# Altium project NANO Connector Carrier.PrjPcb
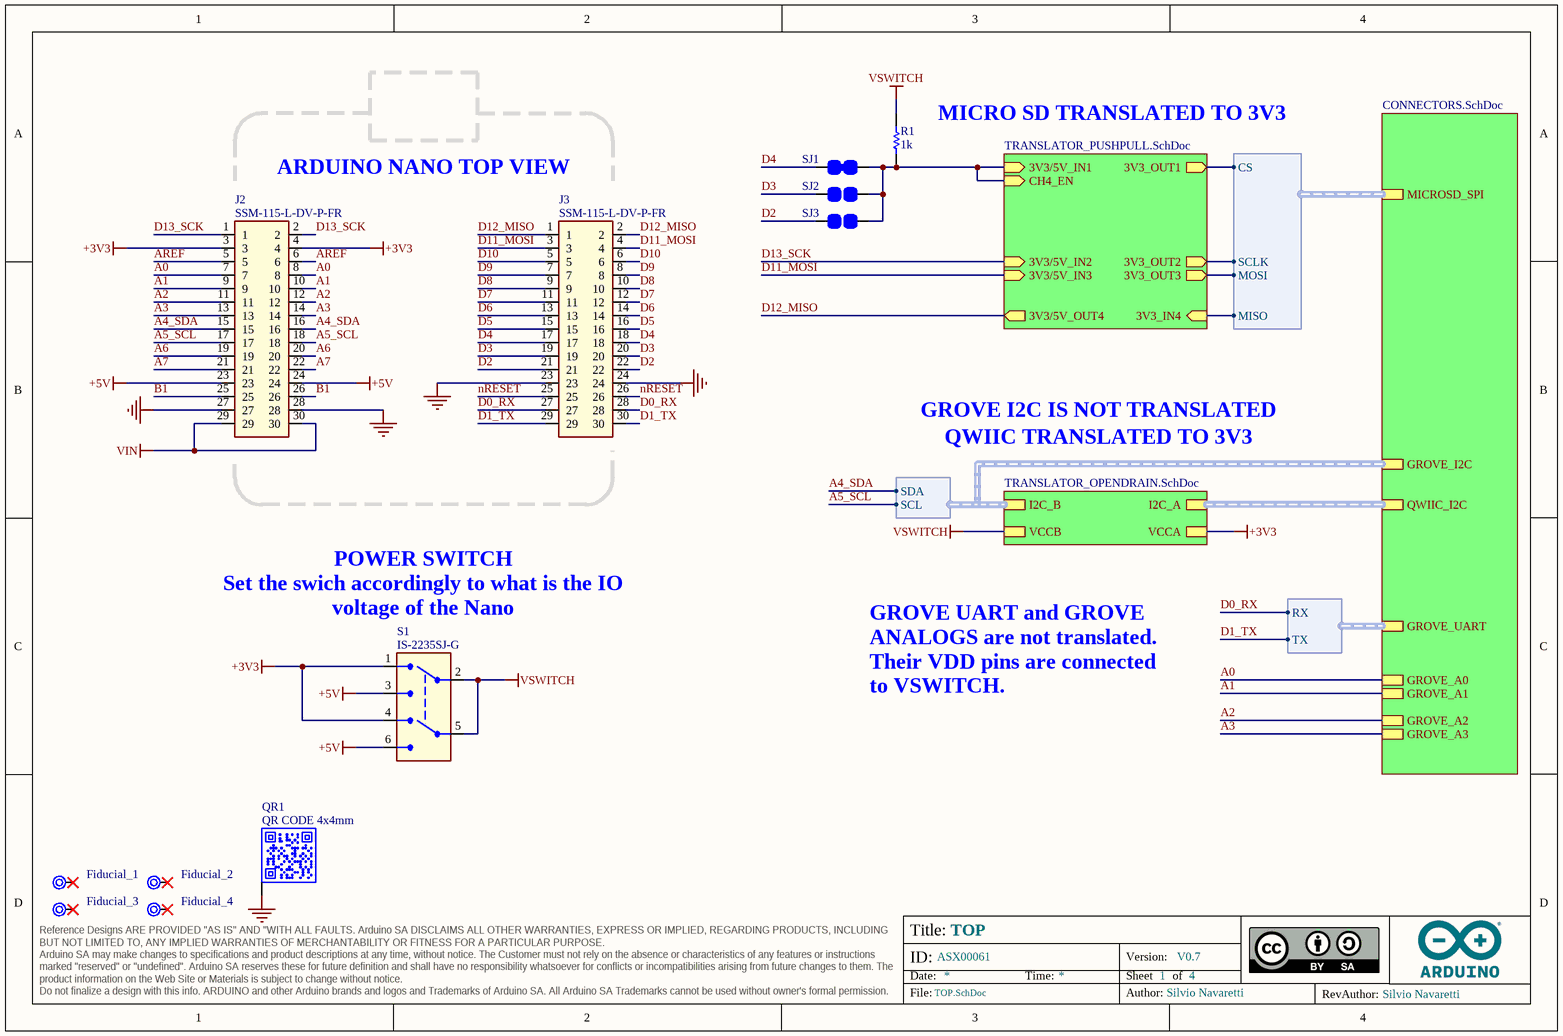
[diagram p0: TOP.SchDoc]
VIA_THROUGH_PAD_MM: 0.6; VIA_THROUGH_HOLE_MM: 0.3; VIA_THROUGH: X; VIA_5_PAD_MM: _; VIA_5_HOLE_MM: _; VIA_5: _; VIA_4_PAD_MM: _; VIA_4_HOLE_MM: _; VIA_4: _; VIA_3_PAD_MM: _; VIA_3_HOLE_MM: _; VIA_3: _; VIA_2_PAD_MM: _; VIA_2_HOLE_MM: _; VIA_2: _; VIA_1_PAD_MM: _; VIA_1_HOLE_MM: _; VIA_1: _; VERSION: V0.7; TRACK_MIN_WIDTH_OUTER: 0.15mm; TRACK_MIN_WIDTH_INNER: 0.15mm; SKU: ASX00061; PANEL_TABS: _; PANEL_SIZE: 162.23mmx182mm; PANEL_SCORING: X; PANEL_REQUESTED: _; PANEL_PROVIDED: X; PANEL_NUMBER_OF_FIGURES: 15; PANEL_NOT_REQUESTED: _; PANEL_MILLING: X; INSULATION_MIN_OUTER: 0.15mm; INSULATION_MIN_INNER: 0.15mm; FINISH_TBD: _; FINISH_TABS: _; FINISH_SOLDERMASK_TOP: X; FINISH_SOLDERMASK_PEELABLE_TOP: _; FINISH_SOLDERMASK_PEELABLE_COLOR: _; FINISH_SOLDERMASK_PEELABLE_BOTTOM: _; FINISH_SOLDERMASK_COLOR: BLUE; FINISH_SOLDERMASK_BOTTOM: X; FINISH_SN/PB: _; FINISH_SILK_TOP: X; FINISH_SILK_COLOR: WHITE; FINISH_SILK_BOTTOM: X; FINISH_NI/AU: _; FINISH_HAL_LF: X; FINISH_HAL: _; FINISH_ENIG: _; FINISH_EDGE_PLATING: _; FINISH_ADJUSTMENTS: _; DRILLS_SOLDER_FILLING: X; DRILLS_SLOT: _; DRILLS_RESIN_FILLING: _; DRILLS_PRESSFIT: _; DRILLS_LASER: _; DRILLS_FULL: X; DRILLS_COPPER_FILLING: _; DRILLS_BURIED: _; DRILLS_BLIND: _; BOARD_INFO_THICKNESS: 1.6mm; BOARD_INFO_TBD: _; BOARD_INFO_RIGID/FLEX: _; BOARD_INFO_RIGID: X; BOARD_INFO_POLYMIDE: _; BOARD_INFO_PCB_SIZE: 43.18mmx27.94mm; BOARD_INFO_NUMBER_OF_LAYERS: 2; BOARD_INFO_IPC_NA: X; BOARD_INFO_IPC3: _; BOARD_INFO_IPC2: _; BOARD_INFO_IPC1: _; BOARD_INFO_FR4_HTG: _; BOARD_INFO_FR4: X; BOARD_INFO_FLEX: _; BOARD_INFO_Er: _; BOARD_INFO_AUTHOR_REV: Silvio Navaretti; BOARD_INFO_AUTHOR: Silvio Navaretti; BOARD_CODENAME: Nano Connector Carrier; ASSEMBLY_THT: _; ASSEMBLY_SMD: X; ASSEMBLY_PRESSFIT: _; ASSEMBLY_BGA: _
4 sheets, 38 parts. Net scope: hierarchical (ports join the sheet entries above them; power ports are global).
Board files: NANO.PcbDoc, NANO_PANEL.PcbDoc
Sheets:
  TOP.SchDoc
    U_CONNECTORS = CONNECTORS.SchDoc
    U_TRANSLATOR_OPENDRAIN = TRANSLATOR_OPENDRAIN.SchDoc
    U_TRANSLATOR_PUSHPULL = TRANSLATOR_PUSHPULL.SchDoc

## Sheet TOP.SchDoc: TOP
size A4; Author: Silvio Navaretti; Revision: V0.1; SheetNumber: 1; SheetTotal: 4; RevAuthor: Silvio Navaretti

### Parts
Fiducial_1  Fiducial mark 1mm with 2mm solder  [Fiducial mark 1mm with circle-Footprint-1]  (value not drawn)  (no BOM)
Fiducial_2  Fiducial mark 1mm with 2mm solder  [Fiducial mark 1mm with circle-Footprint-1]  (value not drawn)  (no BOM)
Fiducial_3  Fiducial mark 1mm with 2mm solder  [Fiducial mark 1mm with circle-Footprint-1]  (value not drawn)  (no BOM)
Fiducial_4  Fiducial mark 1mm with 2mm solder  [Fiducial mark 1mm with circle-Footprint-1]  (value not drawn)  (no BOM)
J2  SSM-115-L-DV-P-FR  [SSM-115-L-DV-P-FR-Footprint-1]
J3  SSM-115-L-DV-P-FR  [SSM-115-L-DV-P-FR-Footprint-1]
QR1  QR CODE 4x4mm  [QR CODE 4x4mm]  (no BOM)
R1  value 1k  [RES-0402]  (hidden comment: CRCW04021K00FKEDC)
S1  IS-2235SJ-G  [IS-2235SJ-G]
SJ1  SOLDER JUMPER CLOSED 0603  [SJ 0603 CLOSED]  (value not drawn)  (no BOM)
SJ2  SOLDER JUMPER OPEN 0603  [SJ]  (value not drawn)  (no BOM)
SJ3  SOLDER JUMPER OPEN 0603  [SJ]  (value not drawn)  (no BOM)

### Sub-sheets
U_CONNECTORS = CONNECTORS.SchDoc: QWIIC_I2C (harness I2C), GROVE_I2C (harness I2C), GROVE_A0, GROVE_A1, GROVE_A2, GROVE_A3, GROVE_UART (harness UART), MICROSD_SPI (harness SPI)
U_TRANSLATOR_OPENDRAIN = TRANSLATOR_OPENDRAIN.SchDoc: I2C_B (harness I2C), I2C_A (harness I2C), VCCA, VCCB
U_TRANSLATOR_PUSHPULL = TRANSLATOR_PUSHPULL.SchDoc: 3V3_OUT1 (out), 3V3_OUT2 (out), 3V3_OUT3 (out), 3V3_IN4 (in), CH4_EN (in), 3V3/5V_IN1 (in), 3V3/5V_OUT4 (out), 3V3/5V_IN2 (in), 3V3/5V_IN3 (in)

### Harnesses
I2C: SDA, SCL
SPI: CS, MISO, MOSI, SCLK
UART: TX, RX

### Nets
+3V3: J2.3 J2.4 S1.1 S1.4 ; sheet U_TRANSLATOR_OPENDRAIN/VCCA
+5V: J2.23 J2.24 S1.3 S1.6
GND: J2.27 J2.28 J3.23 J3.24 QR1.PAD
VIN: J2.29 J2.30
VSWITCH: R1.1 S1.2 S1.5 ; sheet U_TRANSLATOR_OPENDRAIN/VCCB
A0: J2.7 J2.8 ; sheet U_CONNECTORS/GROVE_A0
A1: J2.9 J2.10 ; sheet U_CONNECTORS/GROVE_A1
A2: J2.11 J2.12 ; sheet U_CONNECTORS/GROVE_A2
A3: J2.13 J2.14 ; sheet U_CONNECTORS/GROVE_A3
A4_SDA: J2.15 J2.16 ; sheet U_CONNECTORS/GROVE_I2C.SDA
A5_SCL: J2.17 J2.18 ; sheet U_CONNECTORS/GROVE_I2C.SCL
A6: J2.19 J2.20  [project net A6_1]
A7: J2.21 J2.22  [project net A7_1]
AREF: J2.5 J2.6  [project net AREF_1]
B1: J2.25 J2.26  [project net B1_1]
D0_RX: J3.27 J3.28 ; sheet U_CONNECTORS/GROVE_UART.RX
D1_TX: J3.29 J3.30 ; sheet U_CONNECTORS/GROVE_UART.TX
D2: J3.21 J3.22 SJ3.1  [project net D2_1]
D3: J3.19 J3.20 SJ2.1  [project net D3_1]
D4: J3.17 J3.18 SJ1.1  [project net D4_1]
D5: J3.15 J3.16  [project net D5_1]
D6: J3.13 J3.14  [project net D6_1]
D7: J3.11 J3.12  [project net D7_1]
D8: J3.9 J3.10  [project net D8_1]
D9: J3.7 J3.8  [project net D9_1]
D10: J3.5 J3.6  [project net D10_1]
D11_MOSI: J3.3 J3.4 ; sheet U_TRANSLATOR_PUSHPULL/3V3/5V_IN3
D12_MISO: J3.1 J3.2 ; sheet U_TRANSLATOR_PUSHPULL/3V3/5V_OUT4
D13_SCK: J2.1 J2.2 ; sheet U_TRANSLATOR_PUSHPULL/3V3/5V_IN2
nRESET: J3.25 J3.26  [project net nRESET_1]
NetJ9_2: sheet U_TRANSLATOR_PUSHPULL/3V3_OUT1, sheet U_CONNECTORS/MICROSD_SPI.CS
NetJ9_3: sheet U_TRANSLATOR_PUSHPULL/3V3_OUT3, sheet U_CONNECTORS/MICROSD_SPI.MOSI
NetJ9_5: sheet U_TRANSLATOR_PUSHPULL/3V3_OUT2, sheet U_CONNECTORS/MICROSD_SPI.SCLK
NetJ9_7: sheet U_TRANSLATOR_PUSHPULL/3V3_IN4, sheet U_CONNECTORS/MICROSD_SPI.MISO
NetR1_2: R1.2 SJ1.2 SJ2.2 SJ3.2 ; sheet U_TRANSLATOR_PUSHPULL/CH4_EN, sheet U_TRANSLATOR_PUSHPULL/3V3/5V_IN1

Not connected (* = marked no-connect by the designer): Fiducial_1 1*; Fiducial_2 1*; Fiducial_3 1*; Fiducial_4 1*

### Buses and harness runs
harness sheet U_CONNECTORS/GROVE_I2C = sheet U_TRANSLATOR_OPENDRAIN/I2C_B
harness sheet U_CONNECTORS/QWIIC_I2C = sheet U_TRANSLATOR_OPENDRAIN/I2C_A

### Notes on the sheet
- ARDUINO NANO TOP VIEW
- MICRO SD TRANSLATED TO 3V3
- QWIIC TRANSLATED TO 3V3
- GROVE I2C IS NOT TRANSLATED
- (near S1) POWER SWITCH
  Set the swich accordingly to what is the IO voltage of the Nano
- GROVE UART and GROVE ANALOGS are not translated. Their VDD pins are connected to VSWITCH.

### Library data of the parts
Fiducial_1-Fiducial_4 = UT0024-A.6
J2 J3 = J0295-A.4: CONN SOCKET 2ROW 15POS VERTICAL SMD; Manufacturer: Samtech; Code Arduino: J0295
QR1 = QR-0001-A.5: QR CODE 4x4mm on layer 34 (This is not a component); Code Arduino: QRCODE_4x4mm
R1 = R0007-A.24: RES CHIP 0402 1k 1% 1/16W; Manufacturer: Vishay; Temperature coefficient: 100ppm; Power: 62.5mW; Code Arduino: 0140
S1 = S0018-A.4: SWITCH SLIDE DPDT 200mA; Manufacturer: SWITRONIC; Code Arduino: S0018
SJ1 = UT0039-A.4: Code Arduino: This is not a component
SJ2 SJ3 = UT0038-A.5: Code Arduino: This is not a component

## Sheet CONNECTORS.SchDoc: CONNECTORS
size A4; SheetNumber: 2; SheetTotal: 4
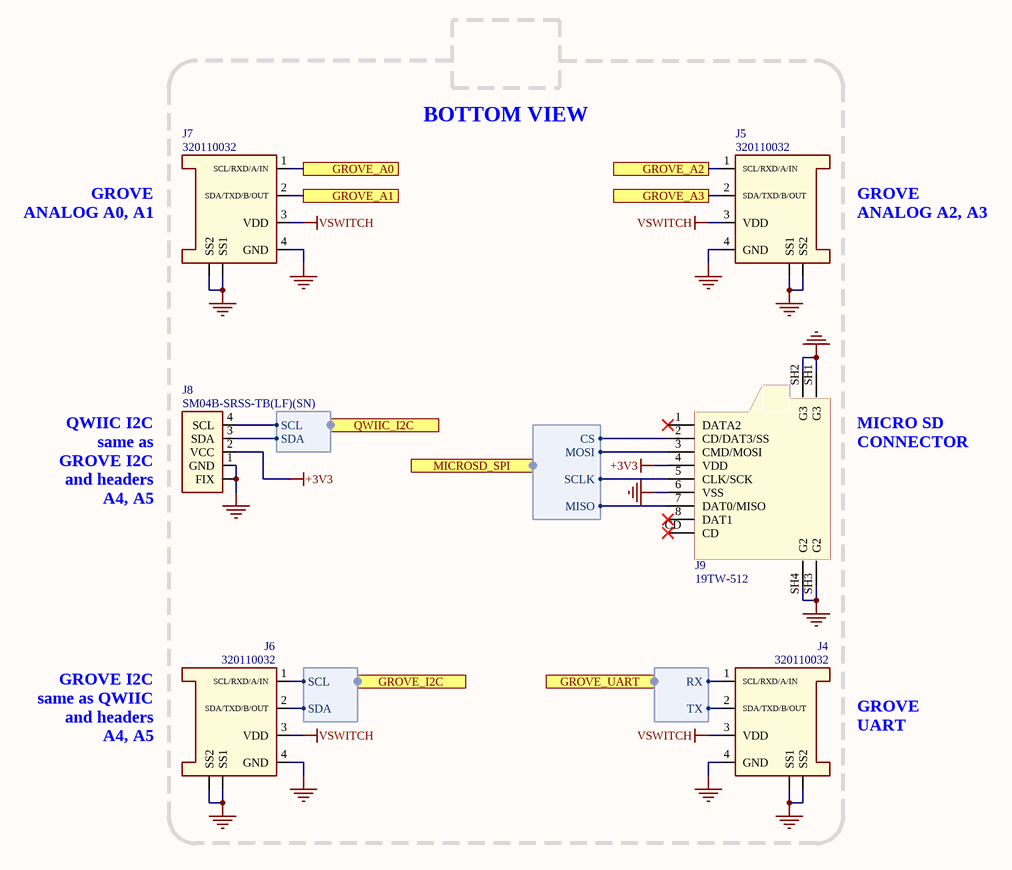
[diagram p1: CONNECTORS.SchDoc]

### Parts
J4  320110032  [320110032-Footprint-1]
J5  320110032  [320110032-Footprint-1]
J6  320110032  [320110032-Footprint-1]
J7  320110032  [320110032-Footprint-1]
J8  SM04B-SRSS-TB(LF)(SN)  [SM04B-SRSS-TB(LF)(SN)-Footprint-1]
J9  19TW-512  [19TW-512]

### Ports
GROVE_A0, GROVE_A1, GROVE_A2, GROVE_A3, GROVE_I2C (harness I2C), GROVE_UART (harness UART), MICROSD_SPI (harness SPI), QWIIC_I2C (harness I2C)

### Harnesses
I2C: SDA, SCL
UART: TX, RX
SPI: CS, MISO, MOSI, SCLK

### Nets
+3V3: J8.2(VCC) J9.4(VDD)
GND: J4.4(GND) J4.SS1 J4.SS2 J5.4(GND) J5.SS1 J5.SS2 J6.4(GND) J6.SS1 J6.SS2 J7.4(GND) J7.SS1 J7.SS2 J8.1(GND) J8.FIX J9.6(VSS) J9.SH1(G3) J9.SH2(G3) J9.SH3(G2) J9.SH4(G2)
VSWITCH: J4.3(VDD) J5.3(VDD) J6.3(VDD) J7.3(VDD)
A0: J7.1(SCL/RXD/A/IN) ; port GROVE_A0
A1: J7.2(SDA/TXD/B/OUT) ; port GROVE_A1
A2: J5.1(SCL/RXD/A/IN) ; port GROVE_A2
A3: J5.2(SDA/TXD/B/OUT) ; port GROVE_A3
A4_SDA: J6.2(SDA/TXD/B/OUT) ; port GROVE_I2C.SDA
A5_SCL: J6.1(SCL/RXD/A/IN) ; port GROVE_I2C.SCL
D0_RX: J4.1(SCL/RXD/A/IN) ; port GROVE_UART.RX
D1_TX: J4.2(SDA/TXD/B/OUT) ; port GROVE_UART.TX
NetJ8_3: J8.3(SDA) ; port QWIIC_I2C.SDA
NetJ8_4: J8.4(SCL) ; port QWIIC_I2C.SCL
NetJ9_2: J9.2(CD/DAT3/SS) ; port MICROSD_SPI.CS
NetJ9_3: J9.3(CMD/MOSI) ; port MICROSD_SPI.MOSI
NetJ9_5: J9.5(CLK/SCK) ; port MICROSD_SPI.SCLK
NetJ9_7: J9.7(DAT0/MISO) ; port MICROSD_SPI.MISO

Not connected (* = marked no-connect by the designer): J9 1(DATA2)* 8(DAT1)* CD*

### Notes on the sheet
- BOTTOM VIEW
- GROVE
  ANALOG A0, A1
- GROVE
  ANALOG A2, A3
- QWIIC I2C same as GROVE I2C and headers
  A4, A5
- (near J9) MICRO SD
  CONNECTOR
- GROVE I2C same as QWIIC and headers
  A4, A5
- GROVE
  UART

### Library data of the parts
J4-J7 = J0274-A.2: CONN GROVE SMD-90D(4+2P-2.0) 320110032 or 215TW-511; Manufacturer: Seeed; Code Arduino: A5410
J8 = J0005-A.2: CONN JST 4POS SIDE 1MM TIN QWIIC; Code Arduino: J0005
J9 = J0370-A.6: T-FLASH CONNECTOR 08PIN SMT 90°; Manufacturer: 4UCON; Code Arduino: J0370

## Sheet TRANSLATOR_OPENDRAIN.SchDoc: Translators OPEN DRAIN
size A4; SheetNumber: 3; SheetTotal: 4
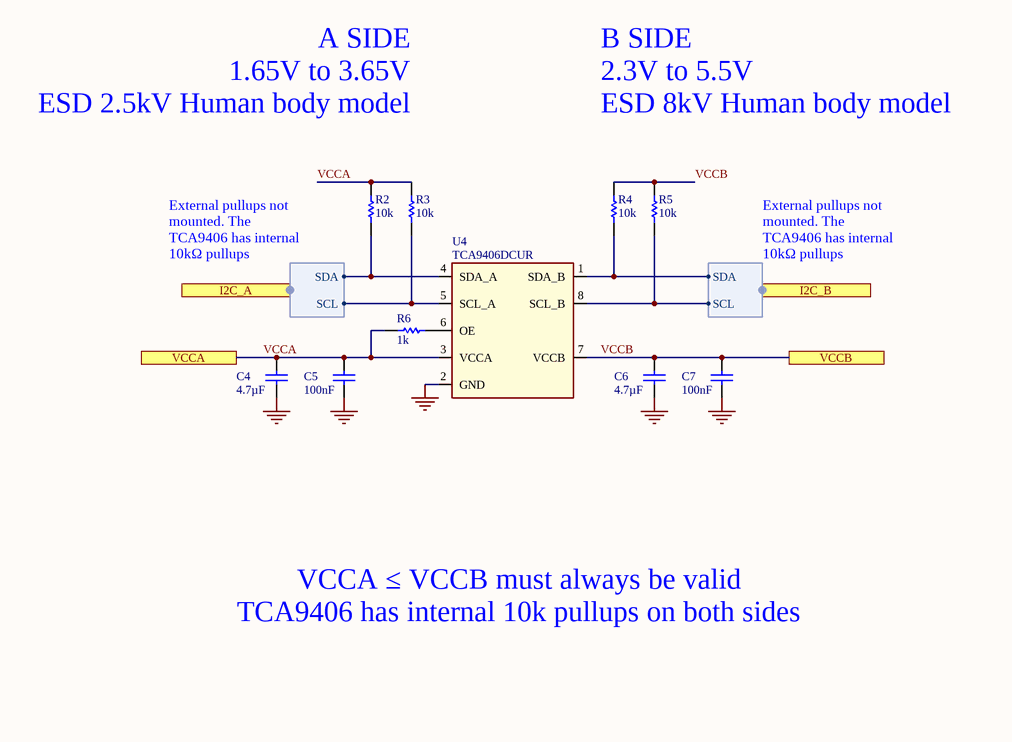
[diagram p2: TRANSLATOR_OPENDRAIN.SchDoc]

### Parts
C4  value 4.7µF  [CAP-0603]  (hidden comment: GRM188R61C475KAAJD)
C5  value 100nF  [CAP-0402]  (hidden comment: 0402B104K160CT)
C6  value 4.7µF  [CAP-0603]  (hidden comment: GRM188R61C475KAAJD)
C7  value 100nF  [CAP-0402]  (hidden comment: 0402B104K160CT)
R2  value 10k  [RES-0603]  (hidden comment: CRCW060310K0JNEAC)
R3  value 10k  [RES-0603]  (hidden comment: CRCW060310K0JNEAC)
R4  value 10k  [RES-0603]  (hidden comment: CRCW060310K0JNEAC)
R5  value 10k  [RES-0603]  (hidden comment: CRCW060310K0JNEAC)
R6  value 1k  [RES-0402]  (hidden comment: CRCW04021K00FKEDC)
U4  TCA9406DCUR  [VSSOP8 pitch 0.5mm body 3.1x2x0.9mm]

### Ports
I2C_A (harness I2C), I2C_B (harness I2C), VCCA, VCCB

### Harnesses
I2C: SDA, SCL

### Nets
GND: C4.1 C5.2 C6.1 C7.2 U4.2(GND)
VCCA: C4.2 C5.1 R2.2 R3.2 R6.2 U4.3(VCCA) ; port VCCA  [project net +3V3]
VCCB: C6.2 C7.1 R4.2 R5.2 U4.7(VCCB) ; port VCCB  [project net VSWITCH]
A4_SDA: R4.1 U4.1(SDA_B) ; port I2C_B.SDA
A5_SCL: R5.1 U4.8(SCL_B) ; port I2C_B.SCL
NetJ8_3: R2.1 U4.4(SDA_A) ; port I2C_A.SDA
NetJ8_4: R3.1 U4.5(SCL_A) ; port I2C_A.SCL
NetR6_1: R6.1 U4.6(OE)

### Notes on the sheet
- A SIDE
  1.65V to 3.65V
  ESD 2.5kV Human body model
- B SIDE
  2.3V to 5.5V
  ESD 8kV Human body model
- External pullups not mounted. The TCA9406 has internal 10kΩ pullups
- VCCA ≤ VCCB must always be valid
  TCA9406 has internal 10k pullups on both sides

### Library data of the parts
C4 C6 = C0054-A.16: CAP CHIP 0603 4.7uF 10% 16V X5R; Manufacturer: Murata; Code Arduino: A5072
C5 C7 = C0012-A.15: CAP CHIP 0402 100nF 10% 16V X7R; Manufacturer: Walsin; Code Arduino: 0132
R2-R5 = R0090-A.22: RES CHIP 0603 10k 5% 1/10W B.5k; Manufacturer: Vishay; Code Arduino: 0028; Power: 100mW; Temperature coefficient: 200ppm
R6 = R0007-A.24: RES CHIP 0402 1k 1% 1/16W; Manufacturer: Vishay; Code Arduino: 0140; Power: 62.5mW; Temperature coefficient: 100ppm
U4 = U0087-A.9: IC Translator 2b,  Push pull, OE, VCCA 1.65V to 3.6V, VCCB 2.3V to 5.5V, internal 10k pullups, Iq 2uA when VCCA or VCCB at 0V, VSSOP8 3.1x2x0.9mm; Manufacturer: Texas Instruments; Code Arduino: A5381

## Sheet TRANSLATOR_PUSHPULL.SchDoc: Translators PUSH PULL
size A4; SheetNumber: 4; SheetTotal: 4
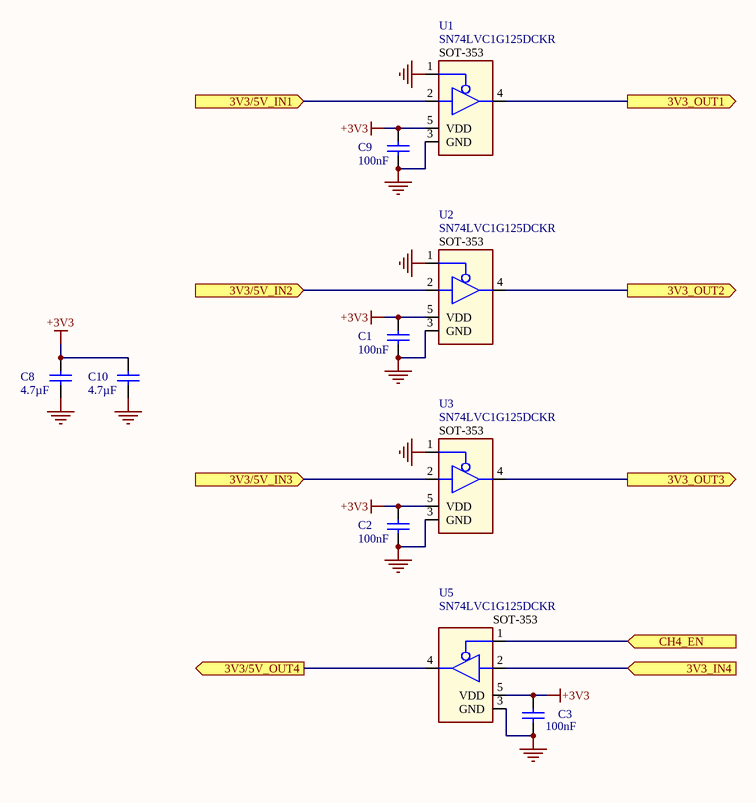
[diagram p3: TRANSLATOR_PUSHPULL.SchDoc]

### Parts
C1  value 100nF  [CAP-0402]  (hidden comment: 0402B104K160CT)
C2  value 100nF  [CAP-0402]  (hidden comment: 0402B104K160CT)
C3  value 100nF  [CAP-0402]  (hidden comment: 0402B104K160CT)
C8  value 4.7µF  [CAP-0603]  (hidden comment: GRM188R61C475KAAJD)
C9  value 100nF  [CAP-0402]  (hidden comment: 0402B104K160CT)
C10  value 4.7µF  [CAP-0603]  (hidden comment: GRM188R61C475KAAJD)
U1  SN74LVC1G125DCKR  [SC70-5]
U2  SN74LVC1G125DCKR  [SC70-5]
U3  SN74LVC1G125DCKR  [SC70-5]
U5  SN74LVC1G125DCKR  [SC70-5]

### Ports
3V3/5V_IN1 (in), 3V3/5V_IN2 (in), 3V3/5V_IN3 (in), 3V3/5V_OUT4 (out), 3V3_IN4 (in), 3V3_OUT1 (out), 3V3_OUT2 (out), 3V3_OUT3 (out), CH4_EN (in)

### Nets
+3V3: C1.1 C2.1 C3.1 C8.2 C9.1 C10.2 U1.5(VDD) U2.5(VDD) U3.5(VDD) U5.5(VDD)
GND: C1.2 C2.2 C3.2 C8.1 C9.2 C10.1 U1.1(~{OE}) U1.3(GND) U2.1(~{OE}) U2.3(GND) U3.1(~{OE}) U3.3(GND) U5.3(GND)
D11_MOSI: U3.2(IN) ; port 3V3/5V_IN3
D12_MISO: U5.4(OUT) ; port 3V3/5V_OUT4
D13_SCK: U2.2(IN) ; port 3V3/5V_IN2
NetJ9_2: U1.4(OUT) ; port 3V3_OUT1
NetJ9_3: U3.4(OUT) ; port 3V3_OUT3
NetJ9_5: U2.4(OUT) ; port 3V3_OUT2
NetJ9_7: U5.2(IN) ; port 3V3_IN4
NetR1_2: U1.2(IN) U5.1(~{OE}) ; port CH4_EN, port 3V3/5V_IN1

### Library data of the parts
C1-C3 C9 = C0012-A.15: as C5 on sheet TRANSLATOR_OPENDRAIN
C8 C10 = C0054-A.16: as C4 on sheet TRANSLATOR_OPENDRAIN
U1-U3 U5 = U0083-A.9: IC BUFFER GATE 3-STATE, 1.65V to 5.5V, nOE,  Iout +-24mA, SC70-5 (SOT353); Manufacturer: Texas Instruments; Code Arduino: 0040

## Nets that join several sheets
+3V3: TOP (J2.3 J2.4 S1.1 S1.4), CONNECTORS (J8.2 J9.4), TRANSLATOR_OPENDRAIN (6 pins), TRANSLATOR_PUSHPULL (10 pins)
GND: TOP (5 pins), CONNECTORS (19 pins), TRANSLATOR_OPENDRAIN (5 pins), TRANSLATOR_PUSHPULL (13 pins)
VSWITCH: TOP (R1.1 S1.2 S1.5), CONNECTORS (J4.3 J5.3 J6.3 J7.3), TRANSLATOR_OPENDRAIN (5 pins)
A0: TOP (J2.7 J2.8), CONNECTORS (J7.1)
A1: TOP (J2.9 J2.10), CONNECTORS (J7.2)
A2: TOP (J2.11 J2.12), CONNECTORS (J5.1)
A3: TOP (J2.13 J2.14), CONNECTORS (J5.2)
A4_SDA: TOP (J2.15 J2.16), CONNECTORS (J6.2), TRANSLATOR_OPENDRAIN (R4.1 U4.1)
A5_SCL: TOP (J2.17 J2.18), CONNECTORS (J6.1), TRANSLATOR_OPENDRAIN (R5.1 U4.8)
D0_RX: TOP (J3.27 J3.28), CONNECTORS (J4.1)
D1_TX: TOP (J3.29 J3.30), CONNECTORS (J4.2)
D11_MOSI: TOP (J3.3 J3.4), TRANSLATOR_PUSHPULL (U3.2)
D12_MISO: TOP (J3.1 J3.2), TRANSLATOR_PUSHPULL (U5.4)
D13_SCK: TOP (J2.1 J2.2), TRANSLATOR_PUSHPULL (U2.2)
NetJ8_3: CONNECTORS (J8.3), TRANSLATOR_OPENDRAIN (R2.1 U4.4)
NetJ8_4: CONNECTORS (J8.4), TRANSLATOR_OPENDRAIN (R3.1 U4.5)
NetJ9_2: CONNECTORS (J9.2), TRANSLATOR_PUSHPULL (U1.4)
NetJ9_3: CONNECTORS (J9.3), TRANSLATOR_PUSHPULL (U3.4)
NetJ9_5: CONNECTORS (J9.5), TRANSLATOR_PUSHPULL (U2.4)
NetJ9_7: CONNECTORS (J9.7), TRANSLATOR_PUSHPULL (U5.2)
NetR1_2: TOP (R1.2 SJ1.2 SJ2.2 SJ3.2), TRANSLATOR_PUSHPULL (U1.2 U5.1)

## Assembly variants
ASX00061: not fitted R2 R3 R4 R5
